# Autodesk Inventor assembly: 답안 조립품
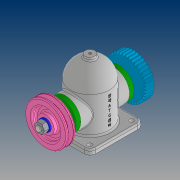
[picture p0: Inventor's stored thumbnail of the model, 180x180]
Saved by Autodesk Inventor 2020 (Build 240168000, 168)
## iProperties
Created: 2021-08
Part Number: 답안 조립품
Document SubType Name: Assembly
Designer: PC312-
Author: PC312-
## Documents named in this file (14)
- C:\Users\PC312-\Desktop\710809V1007\답안 조립품.iam
- C:\Users\PC312-\Desktop\710809V1007\01 본체.ipt
- C:\Users\PC312-\Desktop\710809V1007\커버.ipt
- C:\Users\PC312-\Desktop\710809V1007\베어링 6203.ipt
- C:\Users\PC312-\Desktop\710809V1007\부시.ipt
- C:\Users\PC312-\Desktop\710809V1007\축.ipt
- C:\Users\PC312-\Desktop\710809V1007\키 5x5x12.ipt
- C:\Users\PC312-\Desktop\710809V1007\오일 실 26 38 8.ipt
- C:\Users\PC312-\Desktop\710809V1007\V-벨트풀리.ipt
- V-벨트풀리.ipt
- C:\Users\PC312-\Desktop\710809V1007\스퍼기어.ipt
- C:\Users\PC312-\Desktop\710809V1007\와셔 12x24.ipt
- C:\Users\PC312-\Desktop\710809V1007\너트 M12x1.25.ipt
- C:\Users\PC312-\Desktop\710809V1007\볼트 M4.ipt
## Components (2 placed, 2 different names)
1. 01 본체:1
2. V-벨트풀리:1
